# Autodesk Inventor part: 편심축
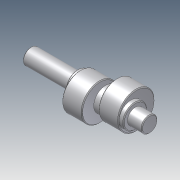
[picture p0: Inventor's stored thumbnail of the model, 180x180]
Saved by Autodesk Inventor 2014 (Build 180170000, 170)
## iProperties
Company: 한국ATC센터
Created: 2014-01
Part Number: 편심축
Document SubType Name: Modeling
Designer: KYOUNG IL JANG
Density: 1 g/cm^3
Material: 강철, 연강
Mass: 122.723 g
Surface Area: 190.471 cm^2
Volume: 122.723 cm^3
Vendor: CBT Solutions
Appearance: 강철
Author: KYOUNG IL JANG
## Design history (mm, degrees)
sketch "스케치1"
  geometry: L1 (70, -32)-(70, 32) reference; L2 (87, -18.2)-(87, 18.2) reference; L3 (-62, 0)-(88, 0); L4 (88, 0)-(88, 10); L5 (88, 10)-(70, 10); L6 (70, 10)-(70, 15); L7 (70, 15)-(-3, 15); L8 (-3, 15)-(-3, 10); L9 (-3, 10)-(-62, 10); L10 (-62, 10)-(-62, 0); L11 (66, 70)-(38, 70) reference; L12 (34, 70)-(6, 70) reference; L13 (52, 70)-(52, 15); L14 (20, 70)-(20, 15); 1 further point
  constraints: 20 end point, 6 perpendicular, 5 point on line, 3 parallel, 2 midpoint, 1 collinear
  dimensions: "d0" = 1 distance from line of L3.end L2; "d1" = 20 diameter of L5 L3; "d2" = 30 diameter of L7 L3; "d3" = 73 distance of L6.end L7.end; "d18" = 150 distance of L3.start L3.end
  node "참조1"
  node "참조2"
  node "참조3"
  node "참조4"
revolve "회전1" stored, may be unused: angle "d4" = 90 deg
node "작업 평면1"
sketch "스케치2"
  geometry: C1 r 15 at (70, 0) reference; C2 r 23 at (63, 0); 1 further point
  constraints: 1 centre point, 1 horizontal alignment
  dimensions: "d6" = 7 distance of C2.centre C1.centre; "d7" = 46 diameter of C2
extrude "돌출1" join sketch "스케치2" stored distance "d8" = 25; taper "d9" = 0 deg
node "작업 평면2"
sketch "스케치3"
  geometry: C1 r 15 at (70, 0) reference; C2 r 23 at (77, 0); 1 further point
  constraints: 1 centre point, 1 horizontal alignment
  dimensions: "d11" = 46 diameter of C2 (= d7); "d12" = 7 distance of C2.centre point (70, 0) (= d6)
extrude "돌출2" join sketch "스케치3" stored distance "d13" = 25; taper "d14" = 0 deg
chamfer "모따기1" distance "d15" = 1; stored, may be unused: second distance "d16" = 2, angle "d17" = 45 deg
node "작업 평면3"
sketch "스케치4"
  geometry: L1 (29.5, 9)-(29.5, -9) reference; L2 (29.5, 3)-(12.5, 3); L3 (12.5, -3)-(29.5, -3); A1 r 3 centre (12.5, 0) between (12.5, 3) and (12.5, -3); 2 further points
  constraints: 4 end point, 2 perpendicular, 2 point on circle, 2 point on line, 2 tangent, 1 centre point, 1 horizontal alignment, 1 midpoint
  dimensions: "d19" = 20 dimension on A1 L1; "d20" = 6 distance between parallel lines of L3 L2
extrude "돌출3" cut sketch "스케치4" distance "d21" = 3.5; taper "d22" = 0 deg
chamfer "모따기2" distance "d23" = 1; stored, may be unused: second distance "d24" = 2, angle "d25" = 45 deg
sketch "스케치5"
  geometry: L1 (8.5, 16)-(8.5, -30) reference; L2 (31.5, 16)-(8.5, 16) reference; L3 (8.5, -7)-(100.304, -7); L4 (63.5, 30)-(40.5, 30) reference; L5 (40.5, 30)-(40.5, -16) reference; L6 (40.5, 7)-(102.22, 7); A1 r 30 centre (20, 45.394) between (14, 16) and (26, 16); A2 r 30 centre (52, 59.394) between (46, 30) and (58, 30); 3 further points
  constraints: 4 end point, 4 midpoint, 4 point on circle, 4 point on line, 2 centre point, 2 parallel, 2 vertical alignment, 1 perpendicular
  dimensions: "d27" = 30 radius of A1; "d28" = 6 distance of A1.start point (20, 16); "d30" = 6 distance of A2.start point (52, 30) (= d28); "d31" = 30 radius of A2 (= d27)
node "솔리드1"
other parameters: "d5" = 0, "d10" = 0
